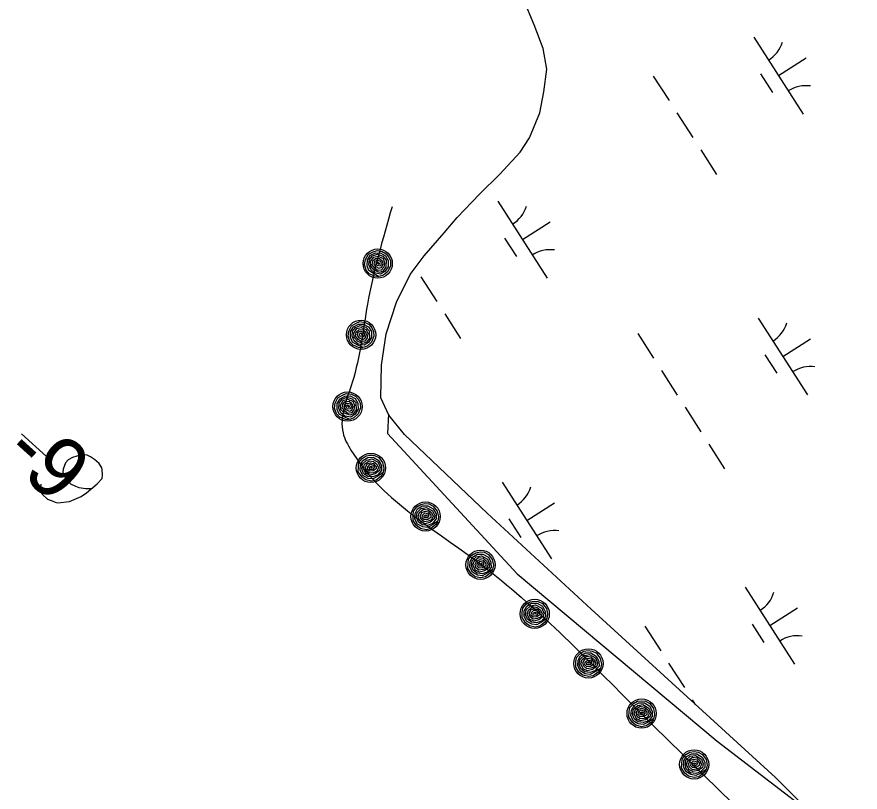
# Model space of a CAD drawing. Extents: x 3962991 to 3983549, y 181631 to 204078.
# Drawn here: x 3977394 to 3977855.3, y 190796.3 to 191220.6 of the extents above; entities that cross this region are included whole.
import ezdxf

# ---------------------------------------------------------------- set-up
doc = ezdxf.new("R2010")
doc.units = 0
for name, color, linetype in [('V-ANNO-MASK', 7, 'Continuous'), ('V-ANNO-MASK2', 7, 'Continuous'), ('V-RIVR-EDGE', 7, 'Continuous'), ('V-RIVR-RANG', 7, 'Continuous'), ('V-RRAP-FSHR', 7, 'Continuous'), ('V-WETL-SWMP', 7, 'Continuous')]:
    doc.layers.add(name, color=color, linetype=linetype)

msp = doc.modelspace()

# ---------------------------------------------------------------- linework, layer by layer
at = {"layer": 'V-ANNO-MASK2'}
msp.add_line((3977396.46, 190992.38), (3977410.14, 190979.97), dxfattribs=at)
msp.add_lwpolyline([(3977407.14, 190964.89), (3977406.75, 190961.32), (3977407.98, 190959.14), (3977410.71, 190956.66), (3977413.38, 190955.67), (3977414.9, 190955), (3977416.41, 190954.7), (3977422.73, 190955.38), (3977429.13, 190958.12), (3977432.02, 190960.12), (3977437.94, 190965.08), (3977440.6, 190968.01), (3977440.88, 190969.89), (3977440.74, 190972.87), (3977440.51, 190973.79), (3977439.08, 190976.15), (3977436.54, 190978.46), (3977434.24, 190979.84), (3977432.51, 190980.69), (3977429.14, 190980.9), (3977424.35, 190979.54), (3977421.99, 190978.12), (3977420.58, 190976.56), (3977419.25, 190973.13), (3977419.14, 190971.45), (3977419.8, 190969.43), (3977421.62, 190966.71), (3977423.37, 190965.12), (3977426.05, 190963.75), (3977427.95, 190963.1), (3977431.72, 190962.54), (3977433.77, 190962.45), (3977434.89, 190962.5)], dxfattribs=at)
at = {"layer": 'V-RIVR-EDGE'}
msp.add_lwpolyline([(3977597.25, 191003.12), (3977596.69, 190992.64), (3977667.63, 190915.78), (3977777, 190824.15), (3977827.25, 190785.72), (3977828.42, 190785.4)], dxfattribs=at)
at = {"layer": 'V-RRAP-FSHR'}
for points in [[(3977591.83, 191078.29), (3977589.79, 191078.69), (3977586.81, 191080.04), (3977585.13, 191082.01), (3977584.25, 191085.1), (3977584.73, 191087.81), (3977586.31, 191090.73), (3977588.92, 191092), (3977591.06, 191092.79), (3977593.84, 191092.24), (3977596.02, 191090.96), (3977597.49, 191089.11), (3977598.33, 191087.06), (3977598.39, 191084.45), (3977596.96, 191081.28), (3977594.51, 191079.24), (3977592.22, 191078.53), (3977589.1, 191080.16), (3977586.61, 191081.78), (3977585.61, 191084.39), (3977585.73, 191087.62), (3977587.52, 191090.15), (3977590.26, 191091.43), (3977593.05, 191091.38), (3977595.7, 191089.81), (3977597.16, 191087.21), (3977597.04, 191083.77), (3977595.28, 191081.19), (3977592.87, 191079.78), (3977589.58, 191080.52), (3977587.55, 191082.39), (3977586.47, 191085.02), (3977586.88, 191087.75), (3977588.6, 191089.76), (3977591.19, 191090.71), (3977594.16, 191089.68), (3977595.96, 191087.48), (3977595.91, 191083.6), (3977594.12, 191081.39), (3977592.31, 191080.8), (3977589.52, 191082.05), (3977587.62, 191084.21), (3977587.51, 191086.66), (3977589.26, 191089.14), (3977591.58, 191089.61), (3977594.4, 191088.36), (3977595.18, 191086.08), (3977594.73, 191083.69), (3977593.37, 191082.01), (3977591.31, 191081.86), (3977589.75, 191083.1), (3977588.42, 191084.98), (3977588.81, 191087.02), (3977590.21, 191088.39), (3977592.4, 191088.44), (3977593.83, 191087.17), (3977594.27, 191085.46), (3977593.42, 191083.41), (3977592.22, 191082.84), (3977590.48, 191083.82), (3977589.44, 191085.45), (3977589.76, 191086.84), (3977591.19, 191087.48), (3977592.98, 191086.93), (3977593.34, 191085.34), (3977592.68, 191084.17), (3977591.06, 191084.46), (3977590.35, 191085.94), (3977591.35, 191086.56), (3977592.27, 191085.88), (3977592.26, 191085.03), (3977591.37, 191085.56)], [(3977583.01, 191039.38), (3977580.96, 191039.69), (3977577.93, 191040.92), (3977576.17, 191042.81), (3977575.16, 191045.86), (3977575.53, 191048.6), (3977576.99, 191051.58), (3977579.55, 191052.96), (3977581.65, 191053.83), (3977584.45, 191053.39), (3977586.69, 191052.21), (3977588.23, 191050.42), (3977589.15, 191048.41), (3977589.32, 191045.8), (3977588.02, 191042.58), (3977585.66, 191040.44), (3977583.39, 191039.63), (3977580.21, 191041.13), (3977577.66, 191042.65), (3977576.55, 191045.21), (3977576.54, 191048.45), (3977578.22, 191051.05), (3977580.91, 191052.43), (3977583.7, 191052.51), (3977586.41, 191051.04), (3977587.97, 191048.5), (3977588, 191045.06), (3977586.34, 191042.42), (3977583.99, 191040.91), (3977580.68, 191041.51), (3977578.57, 191043.3), (3977577.38, 191045.88), (3977577.69, 191048.62), (3977579.32, 191050.7), (3977581.87, 191051.76), (3977584.88, 191050.86), (3977586.76, 191048.73), (3977586.88, 191044.85), (3977585.18, 191042.57), (3977583.39, 191041.9), (3977580.55, 191043.03), (3977578.57, 191045.12), (3977578.36, 191047.56), (3977580, 191050.11), (3977582.3, 191050.68), (3977585.17, 191049.54), (3977586.04, 191047.29), (3977585.69, 191044.89), (3977584.4, 191043.15), (3977582.35, 191042.93), (3977580.74, 191044.1), (3977579.33, 191045.92), (3977579.64, 191047.98), (3977580.99, 191049.4), (3977583.17, 191049.54), (3977584.65, 191048.33), (3977585.16, 191046.64), (3977584.4, 191044.56), (3977583.22, 191043.94), (3977581.44, 191044.85), (3977580.33, 191046.43), (3977580.6, 191047.83), (3977582, 191048.53), (3977583.81, 191048.06), (3977584.23, 191046.48), (3977583.62, 191045.29), (3977582, 191045.51), (3977581.22, 191046.96), (3977582.2, 191047.62), (3977583.14, 191046.98), (3977583.17, 191046.13), (3977582.26, 191046.62)], [(3977575.8, 191000.08), (3977573.74, 191000.35), (3977570.69, 191001.52), (3977568.89, 191003.38), (3977567.83, 191006.41), (3977568.14, 191009.15), (3977569.55, 191012.16), (3977572.08, 191013.59), (3977574.16, 191014.5), (3977576.98, 191014.12), (3977579.23, 191012.98), (3977580.81, 191011.22), (3977581.77, 191009.22), (3977581.99, 191006.61), (3977580.74, 191003.37), (3977578.42, 191001.19), (3977576.18, 191000.33), (3977572.97, 191001.78), (3977570.39, 191003.25), (3977569.23, 191005.79), (3977569.16, 191009.02), (3977570.79, 191011.66), (3977573.45, 191013.09), (3977576.24, 191013.21), (3977578.98, 191011.8), (3977580.59, 191009.29), (3977580.68, 191005.85), (3977579.07, 191003.18), (3977576.75, 191001.62), (3977573.43, 191002.17), (3977571.29, 191003.91), (3977570.05, 191006.47), (3977570.3, 191009.22), (3977571.89, 191011.33), (3977574.42, 191012.43), (3977577.45, 191011.59), (3977579.38, 191009.49), (3977579.56, 191005.62), (3977577.9, 191003.31), (3977576.13, 191002.61), (3977573.27, 191003.68), (3977571.25, 191005.74), (3977570.99, 191008.17), (3977572.59, 191010.75), (3977574.88, 191011.36), (3977577.77, 191010.27), (3977578.68, 191008.05), (3977578.38, 191005.63), (3977577.12, 191003.88), (3977575.07, 191003.61), (3977573.44, 191004.75), (3977572, 191006.55), (3977572.27, 191008.61), (3977573.59, 191010.06), (3977575.77, 191010.24), (3977577.27, 191009.06), (3977577.81, 191007.38), (3977577.09, 191005.28), (3977575.92, 191004.64), (3977574.12, 191005.52), (3977572.99, 191007.07), (3977573.23, 191008.49), (3977574.62, 191009.21), (3977576.44, 191008.77), (3977576.89, 191007.2), (3977576.3, 191006), (3977574.67, 191006.19), (3977573.87, 191007.62), (3977574.83, 191008.3), (3977575.78, 191007.67), (3977575.83, 191006.83), (3977574.91, 191007.3)], [(3977594.37, 190970.76), (3977593.08, 190969.13), (3977590.5, 190967.12), (3977587.98, 190966.54), (3977584.84, 190967.19), (3977582.65, 190968.86), (3977580.79, 190971.62), (3977580.87, 190974.52), (3977581.16, 190976.78), (3977582.94, 190978.99), (3977585.08, 190980.34), (3977587.39, 190980.78), (3977589.6, 190980.58), (3977591.95, 190979.43), (3977594.09, 190976.69), (3977594.77, 190973.58), (3977594.35, 190971.21), (3977591.46, 190969.2), (3977588.87, 190967.75), (3977586.09, 190968.07), (3977583.29, 190969.67), (3977581.86, 190972.42), (3977582, 190975.44), (3977583.33, 190977.9), (3977585.95, 190979.52), (3977588.93, 190979.61), (3977591.93, 190977.91), (3977593.39, 190975.16), (3977593.53, 190972.37), (3977591.36, 190969.8), (3977588.76, 190968.86), (3977585.93, 190969.11), (3977583.7, 190970.75), (3977582.71, 190973.2), (3977583.07, 190975.93), (3977585.35, 190978.1), (3977588.14, 190978.67), (3977591.56, 190976.83), (3977592.68, 190974.23), (3977592.37, 190972.34), (3977589.98, 190970.45), (3977587.18, 190969.77), (3977584.96, 190970.8), (3977583.56, 190973.5), (3977584.22, 190975.77), (3977586.64, 190977.69), (3977589.02, 190977.33), (3977590.93, 190975.83), (3977591.79, 190973.84), (3977590.97, 190971.95), (3977589.15, 190971.14), (3977586.87, 190970.83), (3977585.24, 190972.12), (3977584.67, 190973.99), (3977585.64, 190975.96), (3977587.42, 190976.64), (3977589.15, 190976.24), (3977590.57, 190974.54), (3977590.52, 190973.21), (3977588.84, 190972.12), (3977586.93, 190971.95), (3977585.84, 190972.88), (3977585.93, 190974.44), (3977587.25, 190975.78), (3977588.82, 190975.35), (3977589.55, 190974.23), (3977588.55, 190972.93), (3977586.91, 190972.98), (3977586.82, 190974.16), (3977587.85, 190974.65), (3977588.6, 190974.26), (3977587.72, 190973.71)], [(3977624.3, 190944.25), (3977623.02, 190942.61), (3977620.46, 190940.58), (3977617.95, 190939.98), (3977614.79, 190940.6), (3977612.59, 190942.26), (3977610.71, 190945), (3977610.77, 190947.9), (3977611.04, 190950.16), (3977612.8, 190952.39), (3977614.93, 190953.75), (3977617.24, 190954.22), (3977619.45, 190954.03), (3977621.81, 190952.9), (3977623.97, 190950.18), (3977624.68, 190947.07), (3977624.27, 190944.7), (3977621.4, 190942.67), (3977618.82, 190941.2), (3977616.04, 190941.49), (3977613.22, 190943.07), (3977611.78, 190945.81), (3977611.89, 190948.83), (3977613.2, 190951.3), (3977615.81, 190952.94), (3977618.79, 190953.05), (3977621.8, 190951.38), (3977623.29, 190948.64), (3977623.45, 190945.85), (3977621.3, 190943.27), (3977618.71, 190942.31), (3977615.87, 190942.54), (3977613.63, 190944.15), (3977612.62, 190946.59), (3977612.96, 190949.33), (3977615.22, 190951.51), (3977618, 190952.11), (3977621.44, 190950.3), (3977622.58, 190947.7), (3977622.29, 190945.82), (3977619.91, 190943.9), (3977617.11, 190943.2), (3977614.89, 190944.21), (3977613.47, 190946.9), (3977614.11, 190949.18), (3977616.51, 190951.12), (3977618.9, 190950.78), (3977620.82, 190949.29), (3977621.7, 190947.31), (3977620.89, 190945.42), (3977619.07, 190944.59), (3977616.79, 190944.26), (3977615.16, 190945.54), (3977614.58, 190947.41), (3977615.53, 190949.38), (3977617.31, 190950.07), (3977619.03, 190949.69), (3977620.47, 190948), (3977620.43, 190946.67), (3977618.76, 190945.57), (3977616.85, 190945.38), (3977615.75, 190946.3), (3977615.83, 190947.86), (3977617.13, 190949.21), (3977618.72, 190948.8), (3977619.45, 190947.68), (3977618.46, 190946.38), (3977616.82, 190946.41), (3977616.72, 190947.59), (3977617.75, 190948.09), (3977618.5, 190947.71), (3977617.62, 190947.15)], [(3977654.29, 190917.72), (3977652.98, 190916.11), (3977650.38, 190914.11), (3977647.86, 190913.56), (3977644.72, 190914.23), (3977642.55, 190915.93), (3977640.71, 190918.7), (3977640.82, 190921.6), (3977641.12, 190923.85), (3977642.92, 190926.05), (3977645.07, 190927.38), (3977647.39, 190927.8), (3977649.6, 190927.58), (3977651.93, 190926.41), (3977654.06, 190923.66), (3977654.71, 190920.54), (3977654.26, 190918.18), (3977651.36, 190916.19), (3977648.76, 190914.76), (3977645.98, 190915.1), (3977643.19, 190916.72), (3977641.79, 190919.49), (3977641.96, 190922.51), (3977643.31, 190924.95), (3977645.94, 190926.55), (3977648.92, 190926.62), (3977651.91, 190924.9), (3977653.35, 190922.13), (3977653.46, 190919.34), (3977651.27, 190916.79), (3977648.66, 190915.87), (3977645.83, 190916.15), (3977643.62, 190917.8), (3977642.65, 190920.26), (3977643.03, 190922.99), (3977645.33, 190925.14), (3977648.12, 190925.69), (3977651.52, 190923.82), (3977652.62, 190921.2), (3977652.3, 190919.32), (3977649.89, 190917.45), (3977647.08, 190916.79), (3977644.88, 190917.84), (3977643.5, 190920.55), (3977644.18, 190922.82), (3977646.61, 190924.72), (3977648.99, 190924.34), (3977650.89, 190922.82), (3977651.73, 190920.83), (3977650.89, 190918.95), (3977649.07, 190918.15), (3977646.78, 190917.85), (3977645.16, 190919.16), (3977644.62, 190921.04), (3977645.6, 190922.99), (3977647.39, 190923.66), (3977649.11, 190923.25), (3977650.52, 190921.54), (3977650.46, 190920.21), (3977648.77, 190919.13), (3977646.85, 190918.98), (3977645.77, 190919.92), (3977645.88, 190921.48), (3977647.2, 190922.8), (3977648.78, 190922.36), (3977649.5, 190921.24), (3977648.48, 190919.95), (3977646.84, 190920.01), (3977646.76, 190921.19), (3977647.8, 190921.67), (3977648.54, 190921.27), (3977647.66, 190920.73)], [(3977683.92, 190890.86), (3977682.61, 190889.24), (3977680.02, 190887.25), (3977677.5, 190886.69), (3977674.35, 190887.36), (3977672.18, 190889.06), (3977670.35, 190891.83), (3977670.45, 190894.73), (3977670.76, 190896.99), (3977672.55, 190899.18), (3977674.71, 190900.51), (3977677.02, 190900.94), (3977679.23, 190900.71), (3977681.57, 190899.54), (3977683.69, 190896.79), (3977684.34, 190893.67), (3977683.9, 190891.31), (3977680.99, 190889.33), (3977678.39, 190887.89), (3977675.62, 190888.23), (3977672.82, 190889.86), (3977671.43, 190892.63), (3977671.59, 190895.64), (3977672.94, 190898.09), (3977675.57, 190899.68), (3977678.55, 190899.75), (3977681.54, 190898.03), (3977682.98, 190895.26), (3977683.09, 190892.47), (3977680.9, 190889.92), (3977678.29, 190889.01), (3977675.46, 190889.28), (3977673.25, 190890.93), (3977672.28, 190893.39), (3977672.66, 190896.12), (3977674.96, 190898.27), (3977677.75, 190898.82), (3977681.16, 190896.96), (3977682.26, 190894.34), (3977681.94, 190892.46), (3977679.52, 190890.58), (3977676.71, 190889.92), (3977674.51, 190890.98), (3977673.13, 190893.68), (3977673.81, 190895.95), (3977676.24, 190897.85), (3977678.62, 190897.47), (3977680.52, 190895.95), (3977681.36, 190893.96), (3977680.52, 190892.08), (3977678.7, 190891.28), (3977676.41, 190890.99), (3977674.8, 190892.29), (3977674.25, 190894.17), (3977675.23, 190896.13), (3977677.02, 190896.79), (3977678.74, 190896.38), (3977680.15, 190894.67), (3977680.09, 190893.34), (3977678.4, 190892.26), (3977676.48, 190892.11), (3977675.4, 190893.05), (3977675.51, 190894.61), (3977676.83, 190895.94), (3977678.41, 190895.49), (3977679.13, 190894.37), (3977678.11, 190893.08), (3977676.47, 190893.14), (3977676.4, 190894.32), (3977677.43, 190894.8), (3977678.17, 190894.41), (3977677.29, 190893.87)], [(3977713.26, 190863.62), (3977711.93, 190862.03), (3977709.31, 190860.07), (3977706.78, 190859.55), (3977703.65, 190860.27), (3977701.5, 190861.99), (3977699.7, 190864.78), (3977699.85, 190867.69), (3977700.18, 190869.94), (3977702.01, 190872.11), (3977704.18, 190873.41), (3977706.5, 190873.8), (3977708.71, 190873.55), (3977711.03, 190872.35), (3977713.11, 190869.56), (3977713.72, 190866.44), (3977713.24, 190864.08), (3977710.31, 190862.13), (3977707.69, 190860.74), (3977704.92, 190861.12), (3977702.15, 190862.78), (3977700.79, 190865.57), (3977701, 190868.58), (3977702.38, 190871.01), (3977705.04, 190872.57), (3977708.02, 190872.59), (3977710.98, 190870.83), (3977712.38, 190868.05), (3977712.46, 190865.25), (3977710.23, 190862.73), (3977707.61, 190861.85), (3977704.78, 190862.17), (3977702.59, 190863.85), (3977701.66, 190866.32), (3977702.08, 190869.05), (3977704.4, 190871.16), (3977707.2, 190871.67), (3977710.58, 190869.76), (3977711.65, 190867.13), (3977711.3, 190865.25), (3977708.86, 190863.41), (3977706.04, 190862.79), (3977703.85, 190863.87), (3977702.52, 190866.6), (3977703.22, 190868.86), (3977705.68, 190870.73), (3977708.06, 190870.32), (3977709.93, 190868.77), (3977710.75, 190866.77), (3977709.88, 190864.89), (3977708.05, 190864.12), (3977705.76, 190863.86), (3977704.16, 190865.19), (3977703.64, 190867.08), (3977704.64, 190869.02), (3977706.44, 190869.66), (3977708.16, 190869.22), (3977709.54, 190867.49), (3977709.46, 190866.16), (3977707.76, 190865.11), (3977705.84, 190864.98), (3977704.77, 190865.93), (3977704.91, 190867.49), (3977706.25, 190868.8), (3977707.81, 190868.34), (3977708.52, 190867.21), (3977707.49, 190865.93), (3977705.85, 190866.01), (3977705.79, 190867.19), (3977706.82, 190867.66), (3977707.56, 190867.26), (3977706.67, 190866.73)], [(3977742.32, 190836.08), (3977740.96, 190834.51), (3977738.3, 190832.61), (3977735.76, 190832.13), (3977732.65, 190832.91), (3977730.53, 190834.68), (3977728.79, 190837.51), (3977728.99, 190840.41), (3977729.37, 190842.65), (3977731.24, 190844.79), (3977733.44, 190846.04), (3977735.77, 190846.39), (3977737.97, 190846.09), (3977740.26, 190844.84), (3977742.29, 190842.02), (3977742.84, 190838.88), (3977742.31, 190836.54), (3977739.34, 190834.65), (3977736.7, 190833.3), (3977733.94, 190833.74), (3977731.2, 190835.45), (3977729.89, 190838.27), (3977730.16, 190841.27), (3977731.59, 190843.67), (3977734.28, 190845.18), (3977737.26, 190845.15), (3977740.18, 190843.33), (3977741.53, 190840.52), (3977741.55, 190837.73), (3977739.27, 190835.25), (3977736.64, 190834.42), (3977733.82, 190834.79), (3977731.66, 190836.52), (3977730.77, 190839.01), (3977731.25, 190841.72), (3977733.62, 190843.79), (3977736.42, 190844.25), (3977739.76, 190842.27), (3977740.78, 190839.62), (3977740.39, 190837.75), (3977737.92, 190835.95), (3977735.09, 190835.39), (3977732.92, 190836.52), (3977731.64, 190839.27), (3977732.39, 190841.51), (3977734.89, 190843.33), (3977737.25, 190842.87), (3977739.1, 190841.29), (3977739.87, 190839.27), (3977738.97, 190837.42), (3977737.12, 190836.68), (3977734.83, 190836.46), (3977733.25, 190837.82), (3977732.77, 190839.72), (3977733.81, 190841.64), (3977735.63, 190842.25), (3977737.33, 190841.78), (3977738.68, 190840.02), (3977738.58, 190838.69), (3977736.85, 190837.67), (3977734.93, 190837.58), (3977733.88, 190838.56), (3977734.04, 190840.11), (3977735.41, 190841.4), (3977736.97, 190840.9), (3977737.65, 190839.75), (3977736.6, 190838.5), (3977734.96, 190838.62), (3977734.92, 190839.8), (3977735.97, 190840.24), (3977736.7, 190839.82), (3977735.8, 190839.31)], [(3977771.04, 190808.24), (3977769.68, 190806.67), (3977767.02, 190804.76), (3977764.48, 190804.29), (3977761.37, 190805.07), (3977759.25, 190806.84), (3977757.51, 190809.67), (3977757.71, 190812.57), (3977758.09, 190814.8), (3977759.96, 190816.95), (3977762.16, 190818.2), (3977764.49, 190818.55), (3977766.69, 190818.25), (3977768.98, 190817), (3977771.01, 190814.18), (3977771.56, 190811.04), (3977771.03, 190808.7), (3977768.06, 190806.81), (3977765.42, 190805.46), (3977762.66, 190805.9), (3977759.92, 190807.61), (3977758.61, 190810.43), (3977758.88, 190813.43), (3977760.31, 190815.83), (3977763, 190817.34), (3977765.98, 190817.31), (3977768.9, 190815.49), (3977770.25, 190812.68), (3977770.27, 190809.88), (3977767.99, 190807.41), (3977765.36, 190806.58), (3977762.54, 190806.95), (3977760.38, 190808.68), (3977759.49, 190811.17), (3977759.97, 190813.88), (3977762.33, 190815.95), (3977765.14, 190816.4), (3977768.48, 190814.43), (3977769.5, 190811.77), (3977769.11, 190809.91), (3977766.64, 190808.11), (3977763.81, 190807.55), (3977761.64, 190808.67), (3977760.36, 190811.43), (3977761.11, 190813.67), (3977763.6, 190815.49), (3977765.97, 190815.03), (3977767.82, 190813.45), (3977768.59, 190811.43), (3977767.69, 190809.58), (3977765.84, 190808.84), (3977763.54, 190808.62), (3977761.97, 190809.98), (3977761.49, 190811.88), (3977762.53, 190813.8), (3977764.35, 190814.4), (3977766.05, 190813.93), (3977767.4, 190812.18), (3977767.3, 190810.85), (3977765.58, 190809.83), (3977763.65, 190809.74), (3977762.6, 190810.72), (3977762.77, 190812.27), (3977764.13, 190813.55), (3977765.69, 190813.06), (3977766.37, 190811.91), (3977765.31, 190810.65), (3977763.68, 190810.77), (3977763.64, 190811.95), (3977764.69, 190812.4), (3977765.42, 190811.98), (3977764.52, 190811.47)]]:
    msp.add_lwpolyline(points, dxfattribs=at)
for centre in [(3977591.39, 191085.6), (3977582.28, 191046.66), (3977574.93, 191007.35), (3977587.69, 190973.75), (3977617.59, 190947.19), (3977647.63, 190920.77), (3977677.26, 190893.91), (3977706.65, 190866.77), (3977735.77, 190839.35), (3977764.49, 190811.51)]:
    msp.add_circle(centre, 8, dxfattribs=at)
msp.add_spline([(3977599.23, 191116.63), (3977585.78, 191063.38), (3977577.44, 191020.54), (3977572.43, 190992.91), (3977576.74, 190983.51), (3977645.06, 190923.1), (3977728.7, 190846.21), (3977855.29, 190723.49)], degree=3, dxfattribs=at)
at = {"layer": 'V-WETL-SWMP'}
for p, q in [((3977676.93, 191216.27), (3977671.34, 191229.84)), ((3977681.91, 191203.28), (3977676.93, 191216.27)), ((3977797.06, 191209.53), (3977824.04, 191167.44)), ((3977683.89, 191192.02), (3977681.91, 191203.28)), ((3977810.55, 191188.49), (3977825.7, 191198.2)), ((3977682.33, 191179.51), (3977683.89, 191192.02)), ((3977742.15, 191188.24), (3977750.79, 191174.77)), ((3977800.82, 191189.37), (3977807.29, 191179.27)), ((3977680.15, 191168.18), (3977682.33, 191179.51)), ((3977674.45, 191154.41), (3977680.15, 191168.18)), ((3977755.11, 191168.03), (3977763.74, 191154.56)), ((3977669.23, 191146.59), (3977674.45, 191154.41)), ((3977658.15, 191134.51), (3977669.23, 191146.59)), ((3977768.06, 191147.83), (3977776.69, 191134.36)), ((3977647.05, 191123.61), (3977658.15, 191134.51)), ((3977634.79, 191110.91), (3977647.05, 191123.61)), ((3977657.03, 191119.76), (3977684.01, 191077.67)), ((3977627.8, 191102.47), (3977634.79, 191110.91)), ((3977670.52, 191098.71), (3977685.67, 191108.43)), ((3977616.73, 191089.79), (3977627.8, 191102.47)), ((3977660.79, 191099.6), (3977667.26, 191089.5)), ((3977609.19, 191079.55), (3977616.73, 191089.79)), ((3977601.72, 191064.56), (3977609.19, 191079.55)), ((3977615.07, 191078.26), (3977623.71, 191064.79)), ((3977596.08, 191047.23), (3977601.72, 191064.56)), ((3977628.03, 191058.06), (3977636.66, 191044.59)), ((3977799.48, 191055.81), (3977826.46, 191013.72)), ((3977593.41, 191029.94), (3977596.08, 191047.23)), ((3977733.6, 191047.34), (3977742.23, 191033.87)), ((3977812.97, 191034.76), (3977828.12, 191044.48)), ((3977803.24, 191035.65), (3977809.71, 191025.55)), ((3977593.13, 191012.11), (3977593.41, 191029.94)), ((3977746.55, 191027.13), (3977755.18, 191013.66)), ((3977597.46, 191002.67), (3977593.13, 191012.11)), ((3977759.5, 191006.93), (3977768.14, 190993.46)), ((3977605.97, 190992.12), (3977597.46, 191002.67)), ((3977651.31, 190948.93), (3977605.97, 190992.12)), ((3977772.45, 190986.72), (3977781.09, 190973.25)), ((3977659.44, 190966.04), (3977686.43, 190923.94)), ((3977672.94, 190944.99), (3977688.09, 190954.7)), ((3977708.1, 190896.43), (3977651.31, 190948.93)), ((3977663.2, 190945.88), (3977669.68, 190935.77)), ((3977792.47, 190908.49), (3977819.45, 190866.4)), ((3977808.98, 190804.29), (3977708.1, 190896.43)), ((3977805.96, 190887.45), (3977821.11, 190897.16)), ((3977737.56, 190887.2), (3977746.2, 190873.73)), ((3977796.23, 190888.33), (3977802.7, 190878.23)), ((3977750.52, 190866.99), (3977759.15, 190853.52)), ((3977763.47, 190846.79), (3977764.91, 190844.55)), ((3977826.53, 190786.76), (3977808.98, 190804.29))]:
    msp.add_line(p, q, dxfattribs=at)
for centre, start, end in [((3977795.84, 191211.87), 301.8919, 343.4355), ((3977825.66, 191165.36), 81.8919, 123.4355), ((3977655.81, 191122.1), 301.8919, 343.4355), ((3977685.63, 191075.59), 81.8919, 123.4355), ((3977798.26, 191058.14), 301.8919, 343.4355), ((3977828.08, 191011.64), 81.8919, 123.4355), ((3977658.23, 190968.37), 301.8919, 343.4355), ((3977688.04, 190921.86), 81.8919, 123.4355), ((3977791.25, 190910.83), 301.8919, 343.4355), ((3977821.07, 190864.32), 81.8919, 123.4355)]:
    msp.add_arc(centre, 17.62, start, end, dxfattribs=at)

# ---------------------------------------------------------------- texts
at = {"layer": 'V-ANNO-MASK'}
msp.add_text('-9', height=33.5, rotation=317.7841, dxfattribs=at).set_placement((3977385.12, 190979.88))
at = {"layer": 'V-RIVR-RANG'}
msp.add_text('-9', height=33.5, rotation=317.7841, dxfattribs=at).set_placement((3977385.12, 190979.88))

doc.saveas('drawing.dxf')
